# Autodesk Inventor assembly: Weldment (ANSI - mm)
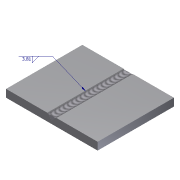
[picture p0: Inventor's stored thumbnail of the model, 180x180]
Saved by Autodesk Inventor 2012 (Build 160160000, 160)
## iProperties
Length Units: 11269
Angle Units: 11283
Time Units: 11279
Mass Units: 11290
Length Display Precision: 3
Angle Display Precision: 2
Part Number: Weldment (ANSI - mm)
Document SubType Name: Weldment
Created: 2002-06
Designer: smithga
Part Number: fig 16-6
Created: 2003-01
Designer: Owner
Control State: 0
Master: False
Shininess: 64.0
Angle Units: 11279
Time Units: 11290
Mass Units: 11283
Compacted: True
Density: 0.0
Volumn: 0.0
Area: 0.0
PropertySet Name: Model Information
Author: Owner
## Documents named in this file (2)
- C:\Users\CadCim\Documents\SAILESH\inventor-2011-fact-prt\c16-inv-2011-prt\c16_inv_2012_prt\fig 16-6\fig 16-6.iam
- C:\Users\CadCim\Documents\SAILESH\inventor-2011-fact-prt\c16-inv-2011-prt\fig-16-6\Part1.ipt
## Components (2 placed, 1 different names)
1. Part1:1 — Mate:1, Flush:1, Flush:2
2. Part1:2 — Mate:1, Flush:1, Flush:2
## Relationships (3: Flush 2, Mate 1)
- Mate:1: Part1:1 ↔ Part1:2
- Flush:1: Part1:1 ↔ Part1:2
- Flush:2: Part1:1 ↔ Part1:2
